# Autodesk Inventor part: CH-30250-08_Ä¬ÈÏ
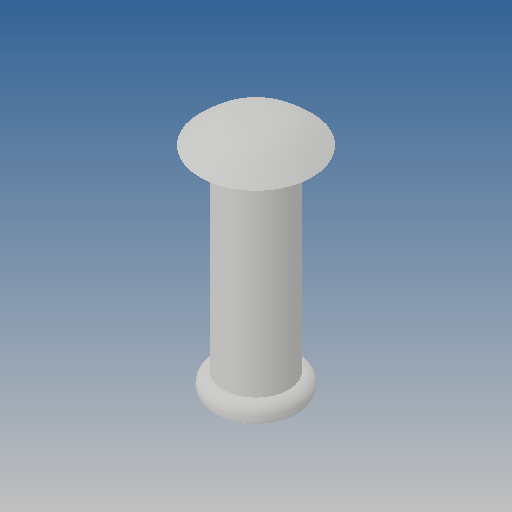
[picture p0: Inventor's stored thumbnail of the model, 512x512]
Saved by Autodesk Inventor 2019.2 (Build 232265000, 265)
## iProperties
Created: 2010-06
Part Number: CH-30250-08_Ä¬ÈÏ
Material: Ogólny
Document SubType Name: Modeling
Designer: CADENGINEERING4
Density: 1 g/cm^3
Appearance: Domyślna
Author: CADENGINEERING4
Revision Number: ÈÎºÎ
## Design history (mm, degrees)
feature "NONE"
node "Bryła1"
